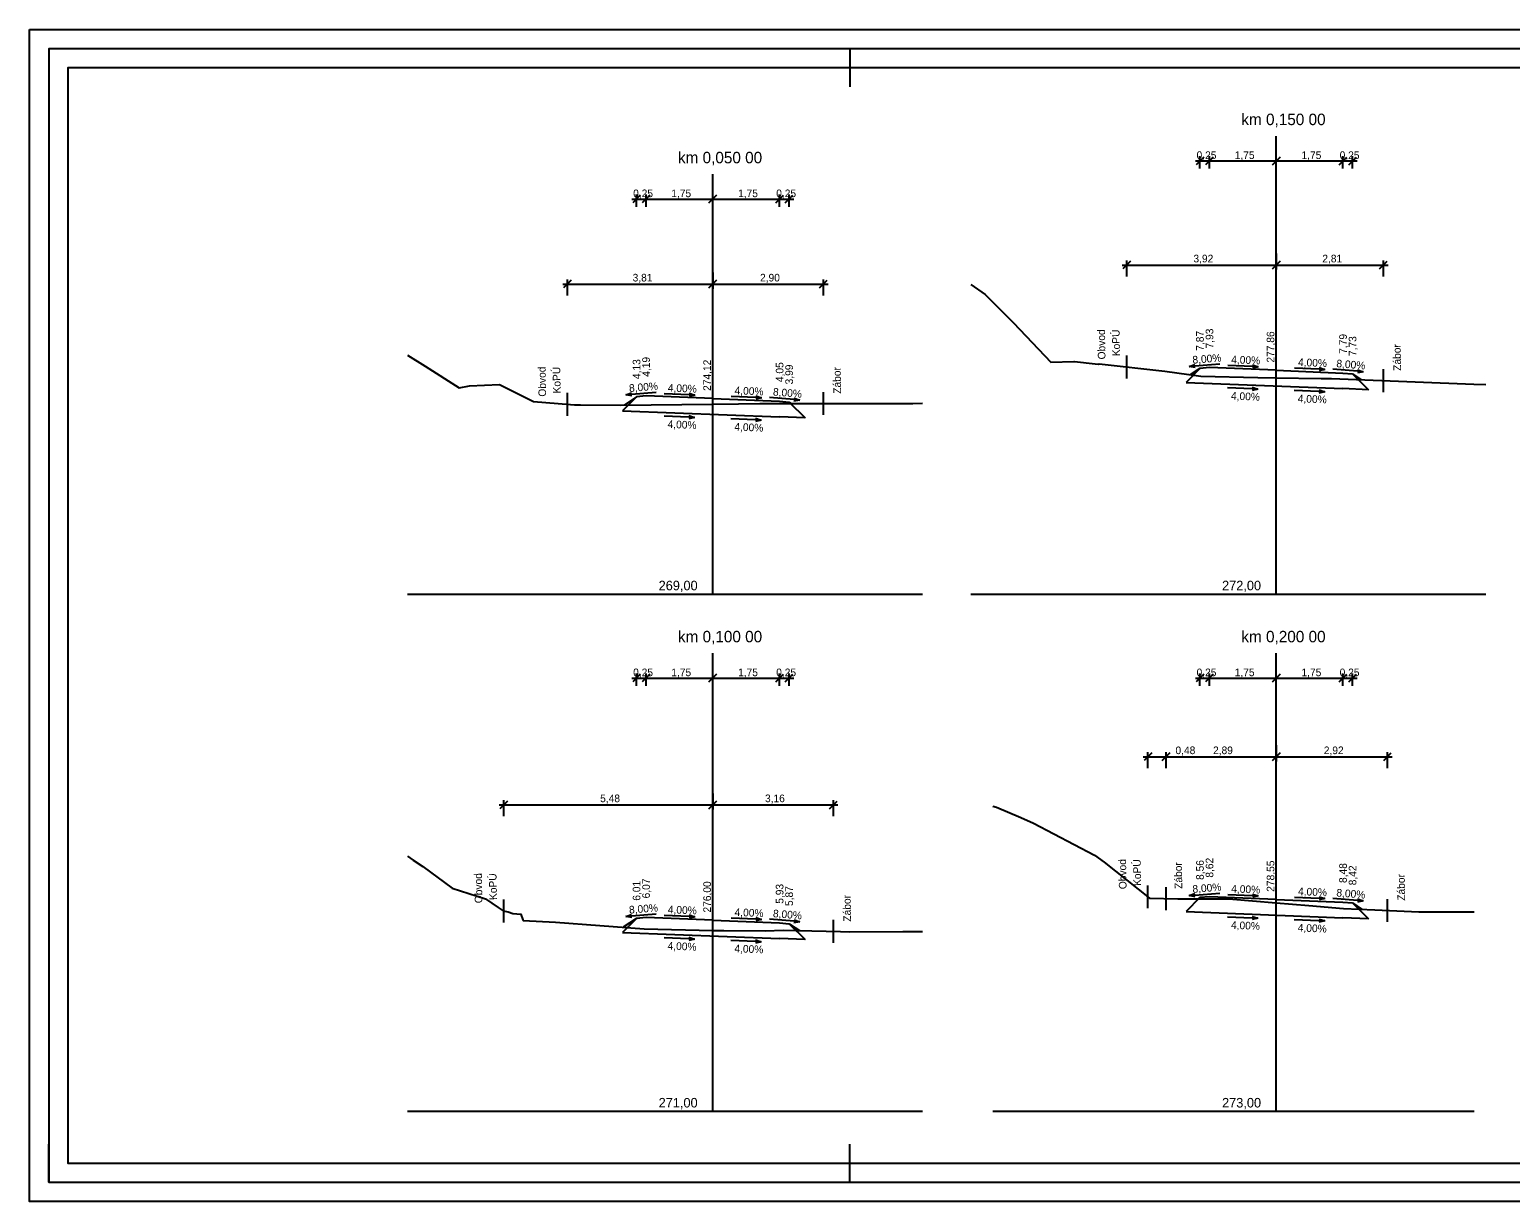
# Model space of a CAD drawing. Extents: x -761098.2 to -761034.2, y -1047998.6 to -1047967.9.
# Drawn here: x -761098.15 to -761059.34, y -1047998.63 to -1047967.93 of the extents above; entities that cross this region are included whole.
import ezdxf

# ---------------------------------------------------------------- set-up
doc = ezdxf.new("R2010")
doc.units = 0
for name, color, linetype in [('C3D-KORIDOR-SPOJNICE', 7, 'Continuous'), ('C3D-POPIS', 7, 'Continuous'), ('C3D-PR-POPIS-TEREN', 7, 'Continuous'), ('C3D-PR-TEREN', 7, 'Continuous'), ('C3D-ZOBPR-NADPIS', 7, 'Continuous'), ('C3D-ZOBPR-OSY', 7, 'Continuous'), ('C3D-ZOBPR-OSY-NADPIS', 7, 'Continuous'), ('Default', 7, 'Continuous'), ('U_formát', 7, 'Continuous'), ('U_rozvržení_rámeček', 7, 'Continuous'), ('Z_Pomocná', 7, 'Continuous')]:
    doc.layers.add(name, color=color, linetype=linetype)

# ---------------------------------------------------------------- blocks, each defined once
blk = doc.blocks.new('_Oblique')
at = {"layer": 'Default'}
blk.add_line((-0.5, -0.5), (0.5, 0.5), dxfattribs=at)
blk = doc.blocks.new('_Open30')
at = {"layer": 'Default'}
for p, q in [((-1, 0.27), (0, 0)), ((0, 0), (-1, -0.27)), ((0, 0), (-1, 0))]:
    blk.add_line(p, q, dxfattribs=at)
blk = doc.blocks.new('U1096')
at = {"layer": 'Default'}
for p, q in [((-630, 0), (-630, -10)), ((-420, 0), (-420, -10)), ((-630, -297), (-630, -287)), ((-420, -297), (-420, -287)), ((-630, -297), (-620, -297))]:
    blk.add_line(p, q, dxfattribs=at)
blk.add_lwpolyline([(0, -297), (0, 0), (-630, 0), (-630, -297)], close=True, dxfattribs=at)
at = {"layer": 'U_formát'}
for points in [[(-635, 5), (5, 5), (5, -302), (-635, -302)], [(-5, -292), (-5, -5), (-625, -5), (-625, -292)]]:
    blk.add_lwpolyline(points, close=True, dxfattribs=at)

msp = doc.modelspace()

# ---------------------------------------------------------------- linework, layer by layer
at = {"layer": 'C3D-KORIDOR-SPOJNICE'}
for p, q in [((-761067.475, -1047976.805), (-761067.84, -1047977.17)), ((-761067.475, -1047976.805), (-761067.727, -1047976.973)), ((-761067.225, -1047976.785), (-761067.475, -1047976.805)), ((-761065.475, -1047976.855), (-761067.225, -1047976.785)), ((-761065.475, -1047976.855), (-761063.725, -1047976.925)), ((-761063.725, -1047976.925), (-761063.475, -1047976.945)), ((-761063.475, -1047976.945), (-761063.058, -1047977.362)), ((-761063.475, -1047976.945), (-761063.242, -1047977.1)), ((-761067.84, -1047977.17), (-761063.725, -1047977.335)), ((-761063.058, -1047977.362), (-761063.725, -1047977.335)), ((-761082.243, -1047977.547), (-761082.608, -1047977.912)), ((-761082.243, -1047977.547), (-761082.57, -1047977.765)), ((-761081.993, -1047977.527), (-761082.243, -1047977.547)), ((-761080.243, -1047977.597), (-761081.993, -1047977.527)), ((-761080.243, -1047977.597), (-761078.493, -1047977.667)), ((-761078.493, -1047977.667), (-761078.243, -1047977.687)), ((-761078.243, -1047977.687), (-761077.826, -1047978.103)), ((-761078.243, -1047977.687), (-761078.185, -1047977.725)), ((-761082.608, -1047977.912), (-761078.493, -1047978.077)), ((-761077.826, -1047978.103), (-761078.493, -1047978.077)), ((-761067.475, -1047990.67), (-761067.84, -1047991.036)), ((-761067.475, -1047990.67), (-761067.528, -1047990.705)), ((-761067.225, -1047990.65), (-761067.475, -1047990.67)), ((-761065.475, -1047990.72), (-761067.225, -1047990.65)), ((-761067.84, -1047991.036), (-761063.725, -1047991.2)), ((-761065.475, -1047990.72), (-761063.725, -1047990.79)), ((-761063.725, -1047990.79), (-761063.475, -1047990.81)), ((-761063.475, -1047990.81), (-761063.058, -1047991.227)), ((-761063.475, -1047990.81), (-761063.223, -1047990.978)), ((-761082.243, -1047991.214), (-761082.608, -1047991.58)), ((-761082.243, -1047991.214), (-761082.594, -1047991.448)), ((-761081.993, -1047991.194), (-761082.243, -1047991.214)), ((-761080.243, -1047991.264), (-761081.993, -1047991.194)), ((-761080.243, -1047991.264), (-761078.493, -1047991.334)), ((-761078.493, -1047991.334), (-761078.243, -1047991.354)), ((-761078.243, -1047991.354), (-761077.826, -1047991.771)), ((-761078.243, -1047991.354), (-761077.975, -1047991.533)), ((-761063.058, -1047991.227), (-761063.725, -1047991.2)), ((-761082.608, -1047991.58), (-761078.493, -1047991.744)), ((-761077.826, -1047991.771), (-761078.493, -1047991.744))]:
    msp.add_line(p, q, dxfattribs=at)
at = {"layer": 'C3D-POPIS'}
for p, q in [((-761067.475, -1047971.567), (-761067.475, -1047971.247)), ((-761067.225, -1047971.567), (-761067.225, -1047971.247)), ((-761065.475, -1047971.567), (-761065.475, -1047971.247)), ((-761063.725, -1047971.567), (-761063.725, -1047971.247)), ((-761063.475, -1047971.567), (-761063.475, -1047971.247)), ((-761067.595, -1047971.367), (-761065.355, -1047971.367)), ((-761065.595, -1047971.367), (-761063.355, -1047971.367)), ((-761082.363, -1047972.367), (-761080.123, -1047972.367)), ((-761082.243, -1047972.567), (-761082.243, -1047972.247)), ((-761081.993, -1047972.567), (-761081.993, -1047972.247)), ((-761080.363, -1047972.367), (-761078.123, -1047972.367)), ((-761080.243, -1047972.567), (-761080.243, -1047972.247)), ((-761078.493, -1047972.567), (-761078.493, -1047972.247)), ((-761078.243, -1047972.567), (-761078.243, -1047972.247)), ((-761082.243, -1047985.118), (-761082.243, -1047984.798)), ((-761081.993, -1047985.118), (-761081.993, -1047984.798)), ((-761080.243, -1047985.118), (-761080.243, -1047984.798)), ((-761078.493, -1047985.118), (-761078.493, -1047984.798)), ((-761078.243, -1047985.118), (-761078.243, -1047984.798)), ((-761067.475, -1047985.118), (-761067.475, -1047984.798)), ((-761067.225, -1047985.118), (-761067.225, -1047984.798)), ((-761065.475, -1047985.118), (-761065.475, -1047984.798)), ((-761063.725, -1047985.118), (-761063.725, -1047984.798)), ((-761063.475, -1047985.118), (-761063.475, -1047984.798)), ((-761082.363, -1047984.918), (-761080.123, -1047984.918)), ((-761080.363, -1047984.918), (-761078.123, -1047984.918)), ((-761067.595, -1047984.918), (-761065.355, -1047984.918)), ((-761065.595, -1047984.918), (-761063.355, -1047984.918))]:
    msp.add_line(p, q, dxfattribs=at)
for points in [[(-761067.605, -1047976.74), (-761066.957, -1047976.688)], [(-761066.097, -1047976.755), (-761066.747, -1047976.729)], [(-761064.347, -1047976.825), (-761064.997, -1047976.799)], [(-761063.345, -1047976.88), (-761063.993, -1047976.828)], [(-761082.373, -1047977.482), (-761081.725, -1047977.43)], [(-761080.865, -1047977.497), (-761081.514, -1047977.471)], [(-761066.104, -1047977.34), (-761066.754, -1047977.314)], [(-761064.354, -1047977.41), (-761065.004, -1047977.384)], [(-761079.115, -1047977.567), (-761079.764, -1047977.541)], [(-761078.113, -1047977.622), (-761078.76, -1047977.57)], [(-761080.872, -1047978.082), (-761081.521, -1047978.056)], [(-761079.122, -1047978.152), (-761079.771, -1047978.126)], [(-761067.605, -1047990.605), (-761066.957, -1047990.554)], [(-761066.097, -1047990.62), (-761066.747, -1047990.594)], [(-761064.347, -1047990.69), (-761064.997, -1047990.664)], [(-761063.345, -1047990.745), (-761063.993, -1047990.694)], [(-761082.373, -1047991.15), (-761081.725, -1047991.098)], [(-761080.865, -1047991.164), (-761081.514, -1047991.138)], [(-761079.115, -1047991.234), (-761079.764, -1047991.208)], [(-761078.113, -1047991.29), (-761078.76, -1047991.238)], [(-761066.104, -1047991.205), (-761066.754, -1047991.179)], [(-761064.354, -1047991.275), (-761065.004, -1047991.249)], [(-761080.872, -1047991.749), (-761081.521, -1047991.723)], [(-761079.122, -1047991.819), (-761079.771, -1047991.793)]]:
    msp.add_lwpolyline(points, dxfattribs=at)
at = {"layer": 'C3D-PR-TEREN'}
for points in [[(-761073.48, -1047974.604), (-761073.108, -1047974.867), (-761072.363, -1047975.612), (-761071.386, -1047976.645), (-761070.78, -1047976.628), (-761070.764, -1047976.627), (-761070.223, -1047976.683), (-761070.13, -1047976.691), (-761070.116, -1047976.689), (-761068.392, -1047976.88), (-761067.454, -1047977.012), (-761065.956, -1047977.042), (-761065.475, -1047977.049), (-761064.295, -1047977.065), (-761064.026, -1047977.068), (-761063.59, -1047977.086), (-761060.294, -1047977.218), (-761059.977, -1047977.23)], [(-761088.248, -1047976.456), (-761087.784, -1047976.748), (-761086.888, -1047977.317), (-761086.623, -1047977.259), (-761085.836, -1047977.228), (-761084.946, -1047977.674), (-761084.3, -1047977.721), (-761083.871, -1047977.763), (-761083.715, -1047977.756), (-761082.672, -1047977.766), (-761080.243, -1047977.739), (-761079.57, -1047977.731), (-761079.01, -1047977.727), (-761078.726, -1047977.726), (-761075.003, -1047977.72), (-761074.745, -1047977.719)], [(-761072.905, -1047988.272), (-761072.804, -1047988.297), (-761072.165, -1047988.568), (-761071.841, -1047988.718), (-761070.242, -1047989.554), (-761069.987, -1047989.741), (-761068.793, -1047990.687), (-761068.05, -1047990.706), (-761066.718, -1047990.704), (-761065.475, -1047990.804), (-761064.617, -1047990.874), (-761063.715, -1047990.954), (-761062.894, -1047990.994), (-761061.741, -1047991.04), (-761060.291, -1047991.045)], [(-761088.248, -1047989.583), (-761088.096, -1047989.688), (-761087.848, -1047989.851), (-761087.079, -1047990.42), (-761086.202, -1047990.7), (-761085.869, -1047990.925), (-761085.741, -1047991.014), (-761085.604, -1047991.046), (-761085.488, -1047991.088), (-761085.275, -1047991.103), (-761085.224, -1047991.254), (-761085.214, -1047991.273), (-761084.365, -1047991.316), (-761082.045, -1047991.49), (-761080.243, -1047991.529), (-761079.954, -1047991.535), (-761078.863, -1047991.538), (-761078.401, -1047991.522), (-761076.894, -1047991.56), (-761076.649, -1047991.564), (-761075.264, -1047991.558), (-761074.925, -1047991.558), (-761074.745, -1047991.559)]]:
    msp.add_lwpolyline(points, dxfattribs=at)
at = {"layer": 'C3D-ZOBPR-OSY'}
for p, q in [((-761065.475, -1047982.717), (-761065.475, -1047970.717)), ((-761080.243, -1047982.717), (-761080.243, -1047971.717)), ((-761088.248, -1047982.717), (-761074.745, -1047982.717)), ((-761073.48, -1047982.717), (-761059.977, -1047982.717)), ((-761080.243, -1047996.268), (-761080.243, -1047984.268)), ((-761065.475, -1047996.268), (-761065.475, -1047984.268)), ((-761088.248, -1047996.268), (-761074.745, -1047996.268)), ((-761072.905, -1047996.268), (-761060.291, -1047996.268))]:
    msp.add_line(p, q, dxfattribs=at)
at = {"layer": 'Default'}
for p, q in [((-761069.392, -1047974.396), (-761069.392, -1047973.976)), ((-761065.475, -1047973.796), (-761065.475, -1047974.216)), ((-761065.475, -1047973.796), (-761065.475, -1047974.216)), ((-761062.665, -1047974.396), (-761062.665, -1047973.976)), ((-761080.243, -1047974.296), (-761080.243, -1047974.716)), ((-761080.243, -1047974.296), (-761080.243, -1047974.716)), ((-761069.512, -1047974.096), (-761065.355, -1047974.096)), ((-761065.595, -1047974.096), (-761062.545, -1047974.096)), ((-761084.174, -1047974.596), (-761080.123, -1047974.596)), ((-761084.054, -1047974.896), (-761084.054, -1047974.476)), ((-761080.363, -1047974.596), (-761077.223, -1047974.596)), ((-761077.343, -1047974.896), (-761077.343, -1047974.476)), ((-761065.475, -1047986.68), (-761065.475, -1047987.1)), ((-761065.475, -1047986.68), (-761065.475, -1047987.1)), ((-761068.959, -1047986.98), (-761068.362, -1047986.98)), ((-761068.839, -1047987.28), (-761068.839, -1047986.86)), ((-761068.482, -1047986.98), (-761065.355, -1047986.98)), ((-761068.362, -1047987.28), (-761068.362, -1047986.86)), ((-761068.362, -1047987.28), (-761068.362, -1047986.86)), ((-761068.362, -1047986.98), (-761067.646, -1047986.98)), ((-761065.595, -1047986.98), (-761062.438, -1047986.98)), ((-761062.558, -1047987.28), (-761062.558, -1047986.86)), ((-761080.243, -1047987.94), (-761080.243, -1047988.36)), ((-761080.243, -1047987.94), (-761080.243, -1047988.36)), ((-761085.844, -1047988.24), (-761080.123, -1047988.24)), ((-761085.724, -1047988.54), (-761085.724, -1047988.12)), ((-761080.363, -1047988.24), (-761076.962, -1047988.24)), ((-761077.082, -1047988.54), (-761077.082, -1047988.12))]:
    msp.add_line(p, q, dxfattribs=at)
at = {"layer": 'Z_Pomocná'}
for points in [[(-761069.392, -1047977.069), (-761069.392, -1047976.769), (-761069.392, -1047976.469)], [(-761062.665, -1047977.423), (-761062.665, -1047977.123), (-761062.665, -1047976.823)], [(-761084.054, -1047978.045), (-761084.054, -1047977.745), (-761084.054, -1047977.445)], [(-761077.343, -1047978.024), (-761077.343, -1047977.724), (-761077.343, -1047977.424)], [(-761068.839, -1047990.95), (-761068.839, -1047990.65), (-761068.839, -1047990.35)], [(-761068.362, -1047990.998), (-761068.362, -1047990.698), (-761068.362, -1047990.398)], [(-761062.558, -1047991.307), (-761062.558, -1047991.007), (-761062.558, -1047990.707)], [(-761085.724, -1047991.318), (-761085.724, -1047991.018), (-761085.724, -1047990.718)], [(-761077.082, -1047991.855), (-761077.082, -1047991.555), (-761077.082, -1047991.255)]]:
    msp.add_lwpolyline(points, dxfattribs=at)

# ---------------------------------------------------------------- block references
at = {"layer": 'C3D-POPIS'}
for name, p, xscale, yscale, rotation in [('_Oblique', (-761067.475, -1047971.367), 0.2, 0.20000000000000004, 180), ('_Oblique', (-761067.225, -1047971.367), 0.2, 0.20000000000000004, 180), ('_Oblique', (-761065.475, -1047971.367), 0.2, 0.20000000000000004, 180), ('_Oblique', (-761082.243, -1047972.367), 0.2, 0.20000000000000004, 180), ('_Oblique', (-761081.993, -1047972.367), 0.2, 0.20000000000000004, 180), ('_Oblique', (-761080.243, -1047972.367), 0.2, 0.20000000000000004, 180), ('_Open30', (-761067.755, -1047976.752), 0.14999999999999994, 0.14999999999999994, -175.4260787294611), ('_Open30', (-761065.947, -1047976.761), 0.15000000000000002, 0.15000000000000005, -2.290610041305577), ('_Open30', (-761064.197, -1047976.831), 0.15000000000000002, 0.15000000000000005, -2.290610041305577), ('_Open30', (-761063.195, -1047976.892), 0.15, 0.15, -4.573921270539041), ('_Open30', (-761082.522, -1047977.494), 0.14999999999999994, 0.14999999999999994, -175.4260787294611), ('_Open30', (-761080.715, -1047977.503), 0.15000000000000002, 0.15000000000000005, -2.290610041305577), ('_Open30', (-761065.954, -1047977.346), 0.15000000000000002, 0.15000000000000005, -2.290610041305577), ('_Open30', (-761064.204, -1047977.416), 0.15000000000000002, 0.15000000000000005, -2.290610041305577), ('_Open30', (-761078.965, -1047977.573), 0.15000000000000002, 0.15000000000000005, -2.290610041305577), ('_Open30', (-761077.963, -1047977.634), 0.15, 0.15, -4.573921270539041), ('_Open30', (-761080.722, -1047978.087), 0.15000000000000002, 0.15000000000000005, -2.290610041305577), ('_Open30', (-761078.972, -1047978.157), 0.15000000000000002, 0.15000000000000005, -2.290610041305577), ('_Oblique', (-761082.243, -1047984.918), 0.2, 0.20000000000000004, 180), ('_Oblique', (-761081.993, -1047984.918), 0.2, 0.20000000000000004, 180), ('_Oblique', (-761080.243, -1047984.918), 0.2, 0.20000000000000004, 180), ('_Oblique', (-761067.475, -1047984.918), 0.2, 0.20000000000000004, 180), ('_Oblique', (-761067.225, -1047984.918), 0.2, 0.20000000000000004, 180), ('_Oblique', (-761065.475, -1047984.918), 0.2, 0.20000000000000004, 180), ('_Open30', (-761067.755, -1047990.617), 0.14999999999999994, 0.14999999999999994, -175.4260787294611), ('_Open30', (-761065.947, -1047990.626), 0.15000000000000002, 0.15000000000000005, -2.290610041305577), ('_Open30', (-761064.197, -1047990.696), 0.15000000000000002, 0.15000000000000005, -2.290610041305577), ('_Open30', (-761063.195, -1047990.757), 0.15, 0.15, -4.573921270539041), ('_Open30', (-761082.522, -1047991.162), 0.14999999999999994, 0.14999999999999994, -175.4260787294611), ('_Open30', (-761080.715, -1047991.17), 0.15000000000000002, 0.15000000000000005, -2.290610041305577), ('_Open30', (-761078.965, -1047991.24), 0.15000000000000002, 0.15000000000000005, -2.290610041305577), ('_Open30', (-761077.963, -1047991.302), 0.15, 0.15, -4.573921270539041), ('_Open30', (-761065.954, -1047991.211), 0.15000000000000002, 0.15000000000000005, -2.290610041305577), ('_Open30', (-761064.204, -1047991.281), 0.15000000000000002, 0.15000000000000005, -2.290610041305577), ('_Open30', (-761080.722, -1047991.755), 0.15000000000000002, 0.15000000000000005, -2.290610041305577), ('_Open30', (-761078.972, -1047991.825), 0.15000000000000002, 0.15000000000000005, -2.290610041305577)]:
    msp.add_blockref(name, p, dxfattribs=dict(at, xscale=xscale, yscale=yscale, rotation=rotation))
at = {"layer": 'C3D-POPIS', "xscale": 0.2, "yscale": 0.20000000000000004}
for p in [(-761065.475, -1047971.367), (-761063.725, -1047971.367), (-761063.475, -1047971.367), (-761080.243, -1047972.367), (-761078.493, -1047972.367), (-761078.243, -1047972.367), (-761080.243, -1047984.918), (-761078.493, -1047984.918), (-761078.243, -1047984.918), (-761065.475, -1047984.918), (-761063.725, -1047984.918), (-761063.475, -1047984.918)]:
    msp.add_blockref('_Oblique', p, dxfattribs=at)
at = {"layer": 'Default', "xscale": 0.2, "yscale": 0.20000000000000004, "rotation": 180}
for p in [(-761069.392, -1047974.096), (-761065.475, -1047974.096), (-761084.054, -1047974.596), (-761080.243, -1047974.596), (-761068.839, -1047986.98), (-761068.362, -1047986.98), (-761065.475, -1047986.98), (-761085.724, -1047988.24), (-761080.243, -1047988.24)]:
    msp.add_blockref('_Oblique', p, dxfattribs=at)
at = {"layer": 'Default', "xscale": 0.2, "yscale": 0.20000000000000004}
for p in [(-761065.475, -1047974.096), (-761062.665, -1047974.096), (-761080.243, -1047974.596), (-761077.343, -1047974.596), (-761068.362, -1047986.98), (-761065.475, -1047986.98), (-761062.558, -1047986.98), (-761080.243, -1047988.24), (-761077.082, -1047988.24)]:
    msp.add_blockref('_Oblique', p, dxfattribs=at)
at = {"layer": 'U_rozvržení_rámeček', "xscale": 0.1, "yscale": 0.10000000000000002}
msp.add_blockref('U1096', (-761034.651, -1047968.429), dxfattribs=at)

# ---------------------------------------------------------------- texts
at = {"layer": 'C3D-POPIS'}
for s, p in [('0,25', (-761067.563, -1047971.318)), ('1,75', (-761066.563, -1047971.318)), ('1,75', (-761064.813, -1047971.318)), ('0,25', (-761063.813, -1047971.318)), ('0,25', (-761082.331, -1047972.318)), ('1,75', (-761081.331, -1047972.318)), ('1,75', (-761079.581, -1047972.318)), ('0,25', (-761078.581, -1047972.318)), ('0,25', (-761082.331, -1047984.869)), ('1,75', (-761081.331, -1047984.869)), ('1,75', (-761079.581, -1047984.869)), ('0,25', (-761078.581, -1047984.869)), ('0,25', (-761067.563, -1047984.869)), ('1,75', (-761066.563, -1047984.869)), ('1,75', (-761064.813, -1047984.869)), ('0,25', (-761063.813, -1047984.869))]:
    msp.add_text(s, height=0.2, dxfattribs=at).set_placement(p)
for s, rotation, p in [('7,87', 90, (-761067.374, -1047976.342)), ('7,93', 90, (-761067.124, -1047976.282)), ('277,86', 90, (-761065.524, -1047976.652)), ('277,86', 90, (-761065.524, -1047976.652)), ('7,79', 90, (-761063.624, -1047976.422)), ('7,73', 90, (-761063.374, -1047976.482)), ('4,13', 90, (-761082.142, -1047977.084)), ('4,19', 90, (-761081.892, -1047977.024)), ('274,12', 90, (-761080.292, -1047977.394)), ('274,12', 90, (-761080.292, -1047977.394)), ('4,05', 90, (-761078.392, -1047977.164)), ('3,99', 90, (-761078.142, -1047977.224)), ('8,00%', 4.5837, (-761067.663, -1047976.682)), ('4,00%', 357.7082, (-761066.657, -1047976.669)), ('4,00%', 357.7082, (-761064.907, -1047976.739)), ('8,00%', 355.4163, (-761063.904, -1047976.772)), ('8,00%', 4.5837, (-761082.431, -1047977.423)), ('4,00%', 357.7082, (-761081.425, -1047977.411)), ('4,00%', 357.7082, (-761079.675, -1047977.481)), ('8,00%', 355.4163, (-761078.672, -1047977.514)), ('4,00%', 357.7094, (-761066.664, -1047977.621)), ('4,00%', 357.7094, (-761064.914, -1047977.691)), ('4,00%', 357.7094, (-761081.431, -1047978.362)), ('4,00%', 357.7094, (-761079.681, -1047978.432)), ('8,56', 90, (-761067.374, -1047990.207)), ('8,62', 90, (-761067.124, -1047990.147)), ('278,55', 90, (-761065.524, -1047990.517)), ('278,55', 90, (-761065.524, -1047990.517)), ('8,48', 90, (-761063.624, -1047990.287)), ('8,42', 90, (-761063.374, -1047990.347)), ('6,01', 90, (-761082.142, -1047990.751)), ('6,07', 90, (-761081.892, -1047990.691)), ('276,00', 90, (-761080.292, -1047991.061)), ('276,00', 90, (-761080.292, -1047991.061)), ('5,93', 90, (-761078.392, -1047990.831)), ('8,00%', 4.5837, (-761067.663, -1047990.547)), ('5,87', 90, (-761078.142, -1047990.891)), ('4,00%', 357.7082, (-761066.657, -1047990.534)), ('4,00%', 357.7082, (-761064.907, -1047990.604)), ('8,00%', 355.4163, (-761063.904, -1047990.637)), ('8,00%', 4.5837, (-761082.431, -1047991.091)), ('4,00%', 357.7082, (-761081.425, -1047991.079)), ('4,00%', 357.7082, (-761079.675, -1047991.149)), ('8,00%', 355.4163, (-761078.672, -1047991.181)), ('4,00%', 357.7094, (-761066.664, -1047991.486)), ('4,00%', 357.7094, (-761064.914, -1047991.556)), ('4,00%', 357.7094, (-761081.431, -1047992.03)), ('4,00%', 357.7094, (-761079.681, -1047992.1))]:
    msp.add_text(s, height=0.2, rotation=rotation, dxfattribs=at).set_placement(p)
at = {"layer": 'C3D-PR-POPIS-TEREN'}
for s, p in [('Obvod ', (-761069.95, -1047976.567)), ('KoPÚ', (-761069.568, -1047976.483)), ('Zábor', (-761062.202, -1047976.866)), ('Obvod ', (-761084.612, -1047977.543)), ('KoPÚ', (-761084.23, -1047977.459)), ('Zábor', (-761076.88, -1047977.467)), ('Obvod ', (-761069.397, -1047990.447)), ('KoPÚ', (-761069.015, -1047990.363)), ('Zábor', (-761067.936, -1047990.439)), ('Obvod ', (-761086.282, -1047990.815)), ('KoPÚ', (-761085.9, -1047990.731)), ('Zábor', (-761062.095, -1047990.75)), ('Zábor', (-761076.619, -1047991.298))]:
    msp.add_text(s, height=0.2, rotation=91.1271, dxfattribs=at).set_placement(p)
at = {"layer": 'C3D-ZOBPR-NADPIS'}
for s, p in [('km 0,150 00', (-761066.389, -1047970.43)), ('km 0,050 00', (-761081.157, -1047971.43)), ('km 0,100 00', (-761081.157, -1047983.981)), ('km 0,200 00', (-761066.389, -1047983.981))]:
    msp.add_text(s, height=0.3, rotation=360, dxfattribs=at).set_placement(p)
at = {"layer": 'C3D-ZOBPR-OSY-NADPIS'}
for s, p in [('269,00', (-761081.663, -1047982.618)), ('272,00', (-761066.895, -1047982.618)), ('271,00', (-761081.663, -1047996.169)), ('273,00', (-761066.895, -1047996.169))]:
    msp.add_text(s, height=0.25, rotation=360, dxfattribs=at).set_placement(p)
at = {"layer": 'Default'}
for s, p in [('3,92', (-761067.645, -1047974.027)), ('2,81', (-761064.267, -1047974.027)), ('3,81', (-761082.345, -1047974.527)), ('2,90', (-761079.005, -1047974.527)), ('0,48', (-761068.116, -1047986.911)), ('2,89', (-761067.131, -1047986.911)), ('2,92', (-761064.228, -1047986.911)), ('5,48', (-761083.196, -1047988.17)), ('3,16', (-761078.875, -1047988.17))]:
    msp.add_text(s, height=0.2, dxfattribs=at).set_placement(p)

doc.saveas('drawing.dxf')
